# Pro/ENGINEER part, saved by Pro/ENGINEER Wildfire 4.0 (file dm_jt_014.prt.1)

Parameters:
  METRIC = "NO"

Other parameters: PITCH, DRILL_POINT_ANGLE, DRILL_DEPTH, DRILL_DIAMETER, THREAD_DIAMETER, THREADS_PER_INCH, THREAD_DEPTH, THREAD_LENGTH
